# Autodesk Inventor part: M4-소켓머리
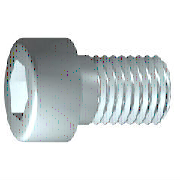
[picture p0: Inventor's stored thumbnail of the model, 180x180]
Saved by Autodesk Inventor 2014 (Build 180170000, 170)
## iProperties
IsCustomPart: 0
Company: 한국ATC센터
Created: 2014-08
Part Number: M4-소켓머리
Material: 강, 연강
Description: 6각머리 태핑 나사
Document SubType Name: Modeling
Standard: KS B 1003
Designer: KYOUNG IL JANG
Standards Organization: KS
Language: ko-KR
Size Designation: M 4 x 12
Categories: <MemberInstance><Categories><Category DisplayName="조임쇠" InternalName="e4da775c-781d-43d5-af7c-5136215cf5a6" Mnemonic="FSTN"><Category DisplayName="볼트" InternalN
Density: 1 g/cm^3
Checked By: KYOUNG IL JANG
Appearance: _시험-금속-강(연마)
Author: KYOUNG IL JANG
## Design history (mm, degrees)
sketch "스케치1"
  geometry: L1 (-1, 0)-(12, 0); L2 (12, 0)-(12, 2); L3 (12, 2)-(1.75, 2); L4 (1.75, 2)-(1.32, 2); L5 (1.32, 2)-(0, 2); L6 (0, 2)-(0, 3.5); L7 (0, 3.5)-(-4, 3.5); L8 (-4, 3.5)-(-4, 1.732); L9 (-4, 1.732)-(-2, 1.732); L10 (-2, 1.732)-(-1, 0); L11 (-7.2, 0)-(15.2, 0) reference; L12 (0, -0.7)-(0, 4.2) reference; L13 (1.75, 2)-(0, 2)
  constraints: 22 end point, 6 parallel, 2 collinear, 2 perpendicular, 1 horizontal, 1 point on line
  dimensions: "d1" = 10.25 distance from line of L3.end L2 (= GEL); "d2" = 0.42952 distance of L4.end L3.end (computed from GAL); "d3" = 4 distance between parallel lines of L8 L6 (= KOH); "d4" = 2 distance of L8.end L9.end (= INTI); "d5" = 60 deg angle of L10 L1; "d6" = 4 diameter of L3 L1 (= GD); "d7" = 4 diameter of L5 L1 (= BDM); "d8" = 3.4641 diameter of L9 L1 (= 1.1547 x SW); "d9" = 7 diameter of L7 L1 (= KOD); "d26" = 12 distance between parallel lines of L12 L2 (= NLG)
revolve "본체" sketch "스케치1" stored, may be unused: angle "d10" = 90 deg
sketch "스케치2"
  geometry: L1 (0, -4.9)-(0, 4.9) reference; L2 (-4.9, 0)-(4.9, 0) reference; L3 (1.732, 0)-(0.866, -1.5); L4 (0.866, -1.5)-(-0.866, -1.5); L5 (-0.866, -1.5)-(-1.732, 0); L6 (-1.732, 0)-(-0.866, 1.5); L7 (-0.866, 1.5)-(0.866, 1.5); L8 (0.866, 1.5)-(1.732, 0); 2 further points
  constraints: 12 end point, 1 coincident, 1 horizontal alignment, 1 point on line, 12 other
extrude "슬롯" join sketch "스케치2" stored distance "d11" = 10; taper "d12" = 0 deg
workplane "Work Plane1"
fillet "Fillet2" dims "d30" = 0.1 (= R)
body "Solid1"
fillet "모깎기1" dims "d17" = 0.4 (= RR)
feature "스레드" dims "d13" = 10.25 (= GEL), "d14" = 0
chamfer "모따기1" distance "d15" = 0.42941 (= -0.5 x SPD + 0.5 x GD); stored, may be unused: second distance "d16" = 0.42941 (= GUL), angle "d27" = 45 deg
other parameters: "GD" = 4 (= NND) [user parameter; used in 2 equation terms], "NLG" = 12 [user parameter; used in 1 equation term], "GEL" = 10.25 [user parameter; used in 2 equation terms], "KOD" = 7 [user parameter; used in 1 equation term], "KOH" = 4 [user parameter; used in 1 equation term], "INTI" = 2 [user parameter; used in 1 equation term], "GAL" = 0.42941 (= 0.61345 x PTC) [user parameter; used in 1 equation term], "GUL" = 0.42941 (= 0.61345 x PTC) [user parameter; used in 1 equation term], "BDM" = 4 (= NND) [user parameter; used in 1 equation term], "SW" = 3 [user parameter; used in 2 equation terms], "RR" = 0.4 [user parameter; used in 1 equation term], "SPD" = 3.14117 (= NND - 1.2269 x PTC) [user parameter; used in 1 equation term], "d19" = 0, "d28" = 0, "d29" = 0, "R" = 0.1 [user parameter; used in 1 equation term], "PHH" = 0.2 [user parameter], "GD1" = 3.14117 (= THREADDIA - 1.2269 x PTC) [user parameter], "THREADDIA" = 4 [user parameter; used in 1 equation term], "FAWI" = 45 deg [user parameter], "TPU" = 14.28571 (computed from PTC) [user parameter], "PTC" = 0.7 [user parameter; used in 5 equation terms], "NND" = 4 [user parameter; used in 3 equation terms], "TOA" = 30 deg [user parameter], "E0" = 3.465 (= 1.155 x SW) [user parameter]
